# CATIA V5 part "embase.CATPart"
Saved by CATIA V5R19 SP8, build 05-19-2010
Part number: embase avant
Bounding box of the stored display mesh (mm): x 0 to 230, y -25 to 25, z 0 to 44
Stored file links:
  G:\EU_thinkMotion\CFAO_2010\MMS_groupe2\MMS_groupe2\A reprendre\rbouchet\rbouchet_Catia\embase.CATPart
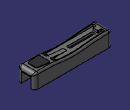
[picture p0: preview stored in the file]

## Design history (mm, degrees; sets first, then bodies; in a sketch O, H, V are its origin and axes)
Set1
  Plane1: type Offset, RefPlane xy-plane, Offset 40
Body1 (main body)
  Sketch1 on yz-plane, origin (0, 0, 0), H (0, 1, 0), V (0, 0, 1)
    line L1 (-25, 0) -> (-25, 45)
    point P1 (-25, 0)
    line L2 (-25, 45) -> (25, 45)
    line L3 (25, 45) -> (25, 0)
    point P4 (25, 0)
    line L4 (25, 0) -> (15, 0)
    line L5 (15, 0) -> (15, 30)
    line L6 (15, 30) -> (-15, 30)
    line L7 (-15, 30) -> (-15, 0)
    line L8 (-15, 0) -> (-25, 0)
    point P9 (-25, 0)
    length L6 = 30
    length L8 = 10
    length L4 = 10
    length L1 = 45
    length L3 = 45
    length L7 = 30
    length L5 = 30
    distance V L5 = 15
    coincidence: P1 H, P4 H, P1 P9
    horizontal: L2 H, L4 H, L6 H, L8 H
    vertical: L3 V, L5 V
  Pad1: profile Sketch1, direction (1, 0, 0), length 230
  Sketch2 on face of Pad1 from Sketch1.L3, origin (0, 25, 0), H (-1, 0, 0), V (0, 0, 1)
    spline S1 through (-230, 43) (-219.336, 42.8754) (-173.9652, 41.983) (-134.5252, 37.5213) (-64.8381, 40.4958) (-28.6601, 42.922) (0, 43)
    reference projected line E1 (-230, 0) -> (-230, 45) from edge [face of Pad1 from Sketch1.L3 | end face of Pad1]
    reference projected line E2 (0, 45) -> (-230, 45) from edge [face of Pad1 from Sketch1.L2 | face of Pad1 from Sketch1.L3]
    reference projected line E3 (0, 45) -> (-230, 45) from edge [face of Pad1 from Sketch1.L2 | face of Pad1 from Sketch1.L3]
    reference projected line E4 (0, 0) -> (0, 45) from edge [start face of Pad1 | face of Pad1 from Sketch1.L3]
    point P1 (0, 43)
    point P2 (-230, 43)
    distance P2 E2 = 2
    distance P1 E3 = 2
    coincidence: P1 V, E1 P2, P1 E4
  Pocket1: profile Sketch2, direction (0, -1, 0), length 230
  Fillet1: radius 5, on edge [face of Pad1 from Sketch1.L3 | face of Pocket1 from Sketch2.S1]; edge [face of Pad1 from Sketch1.L1 | face of Pocket1 from Sketch2.S1]
  Fillet2: radius 10, on edge [start face of Pad1 | face of Pocket1 from Sketch2.S1]; edge [face of Pocket1 from Sketch2.S1 | end face of Pad1]; edge [face of Pad1 from Sketch1.L1 | end face of Pad1]; edge [face of Pad1 from Sketch1.L3 | end face of Pad1]
  Sketch3 on face of Pad1 from Sketch1.L2, origin (0, 0, 45), H (1, 0, 0), V (0, 1, 0)
    line L1 (15, 17.5) -> (15, 7.5)
    line L2 (15, 17.5) -> (165, 17.5)
    line L3 (165, 17.5) -> (165, 6)
    line L4 (165, 6) -> (115, 6)
    line L5 (115, 6) -> (115, -6)
    line L6 (115, -6) -> (165, -6)
    point P7 (165, -6)
    line L7 (165, -6) -> (165, -17.5)
    line L8 (165, -17.5) -> (15, -17.5)
    point P9 (15, -17.5)
    line L9 (15, -17.5) -> (15, -7.5)
    line L10 (15, -7.5) -> (25, -7.5)
    line L11 (25, -7.5) -> (25, 7.5)
    line L12 (25, 7.5) -> (15, 7.5)
    reference projected line E1 (0, 25) -> (230, 25) from edge [face of Pad1 from Sketch1.L2 | face of Pad1 from Sketch1.L3]
    reference projected line E2 (0, 25) -> (0, -25) from edge [start face of Pad1 | face of Pad1 from Sketch1.L2]
    length L2 = 150
    distance L11 L5 = 90
    length L1 = 10
    length L11 = 15
    length L9 = 10
    distance L2 E1 = 7.5
    length L12 = 10
    distance L1 E2 = 15
    distance L4 L6 = 12
    length L3 = 11.5
    vertical: L1 V, L3 V, L5 V, L7 V, L9 V, L11 V
    horizontal: L2 H, L4 H, L6 H, L8 H, L10 H, L12 H
    coincidence: P7 L3, P9 L1
  Pocket2: profile Sketch3, direction (0, 0, -1), length 10
  Fillet3: radius 1, on edge [face of Pocket2 from Sketch3.L1 | face of Pocket2 from Sketch3.L2]; edge [face of Pocket2 from Sketch3.L12 | face of Pocket2 from Sketch3.L1]; edge [face of Pocket2 from Sketch3.L11 | face of Pocket2 from Sketch3.L12]; edge [face of Pocket2 from Sketch3.L10 | face of Pocket2 from Sketch3.L11]; edge [face of Pocket2 from Sketch3.L8 | face of Pocket2 from Sketch3.L9]; edge [face of Pocket2 from Sketch3.L9 | face of Pocket2 from Sketch3.L10]; edge [face of Pocket2 from Sketch3.L2 | face of Pocket2 from Sketch3.L3]; edge [face of Pocket2 from Sketch3.L4 | face of Pocket2 from Sketch3.L5]; edge [face of Pocket2 from Sketch3.L5 | face of Pocket2 from Sketch3.L6]; edge [face of Pocket2 from Sketch3.L6 | face of Pocket2 from Sketch3.L7]; edge [face of Pocket2 from Sketch3.L7 | face of Pocket2 from Sketch3.L8]; edge [face of Pocket2 from Sketch3.L3 | face of Pocket2 from Sketch3.L4]
  Sketch4 on Plane1, origin (0, 0, 40), H (1, 0, 0), V (0, 1, 0)
    line L1 (175, 12.5) -> (175, -12.5)
    point P1 (175, 12.5)
    point P3 (181.043, -13.904)
    point P4 (206.043, -13.904)
    line L2 (212, -8.5) -> (212, 8.5)
    point P5 (212, -8.5)
    point P6 (212, 8.5)
    point P7 (181.1672, 13.2821)
    reference projected line E1 through (220, 0) direction (0, 1) from axis of face of Fillet2
    line L3 (182.4779, 17.5) -> (207.0981, 13.1588)
    point P9 (182.4779, 17.5)
    connectcurve C1
    line L4 (180.9327, -17.5) -> (205.8376, -15.3211)
    point P10 (180.9327, -17.5)
    connectcurve C2
    connectcurve C3
    connectcurve C4
    reference projected line E2 (165, 17.5) -> (165, 6) from edge [face of Pocket2 from Sketch3.L3 | face of Pocket1 from Sketch2.S1]
    reference projected line E3 (15, 17.5) -> (165, 17.5) from edge [face of Pocket2 from Sketch3.L2 | face of Pocket1 from Sketch2.S1]
    reference projected line E4 (15, 17.5) -> (165, 17.5) from edge [face of Pocket2 from Sketch3.L2 | face of Pocket1 from Sketch2.S1]
    reference projected line E5 (165, -17.5) -> (15, -17.5) from edge [face of Pocket2 from Sketch3.L8 | face of Pocket1 from Sketch2.S1]
    reference projected line E6 (165, -17.5) -> (15, -17.5) from edge [face of Pocket2 from Sketch3.L8 | face of Pocket1 from Sketch2.S1]
    reference projected line E7 (15, 17.5) -> (165, 17.5) from edge [face of Pocket2 from Sketch3.L2 | face of Pocket1 from Sketch2.S1]
    length L1 = 25
    distance L2 E1 = 8
    angle L1 L3 = 80
    angle L1 L4 = 85
    distance L1 E2 = 10
    distance E3 P1 = 5
    length L3 = 25
    length L4 = 25
    distance P9 E4 = 0
    distance P10 E5 = 0
    distance P5 E6 = 9
    distance P6 E7 = 9
    vertical: L1 V, L2 V
  Pad2: profile Sketch4, direction (0, 0, 1), length 4
  Fillet4: radius 0.2, on edge [face of Pocket1 from Sketch2.S1 | face of Pad2 from Sketch4.L1]; edge [face of Pocket1 from Sketch2.S1 | face of Pad2 from Sketch4.C4]; edge [face of Pocket1 from Sketch2.S1 | face of Pad2 from Sketch4.L4]; edge [face of Pad2 from Sketch4.C2 | face of Pocket1 from Sketch2.S1]; edge [face of Pad2 from Sketch4.C3 | face of Pocket1 from Sketch2.S1]; edge [face of Pad2 from Sketch4.L3 | face of Pocket1 from Sketch2.S1]; edge [face of Pocket1 from Sketch2.S1 | face of Pad2 from Sketch4.C1]; face of Pocket1 from Sketch2.S1; end face of Pad2
  Sketch5 on face of Pocket2 from Sketch3.L8, origin (0, -17.5, 0), H (-1, 0, 0), V (0, 0, 1)
    circle A1 centre (-160.9607, 38.808) radius 1.5
    point P1 (-160.9607, 38.808)
    reference projected line E1 (-165, 35) -> (-15, 35) from edge [face of Pocket2 from Sketch3.L8 | end face of Pocket2]
    radius A1 = 1.5
    distance P1 E1 = 3.808
  Pocket3: profile Sketch5, direction (0, -1, 0), length 3
  RectPattern1: of Pocket3, direction 1 instances 2, spacing 14.5, along edge [face of Pocket2 from Sketch3.L7 | face of Fillet4] reversed
  RectPattern2: of Pocket3, direction 1 instances 2, spacing 23.5, along edge [face of Pocket2 from Sketch3.L7 | face of Fillet4] reversed
  RectPattern3: of Pocket3, direction 1 instances 2, spacing 38, along edge [face of Pocket2 from Sketch3.L7 | face of Fillet4] reversed
  Sketch6 on end face of Pocket2, origin (0, 0, 35), H (1, 0, 0), V (0, 1, 0)
    line L1 (15, 17.5) -> (155.1781, 17.5)
    line L2 (155.1781, 17.5) -> (155.1781, 6)
    line L3 (155.1781, 6) -> (115, 6)
    line L4 (115, 6) -> (115, -6)
    line L5 (115, -6) -> (155.1781, -6)
    point P6 (155.1781, -6)
    line L6 (155.1781, -6) -> (155.1781, -17.5)
    line L7 (155.1781, -17.5) -> (15, -17.5)
    line L8 (15, -17.5) -> (15, -7.5)
    line L9 (15, -7.5) -> (25, -7.5)
    line L10 (25, -7.5) -> (25, 7.5)
    line L11 (25, 7.5) -> (15, 7.5)
    line L12 (15, 7.5) -> (15, 17.5)
    reference projected line E1 (165.1781, 16.5) -> (165.1781, 7) from edge [face of Fillet4 | face of Pocket1 from Sketch2.S1]
    reference projected line E2 (15, 17.5) -> (165, 17.5) from edge [face of Pocket2 from Sketch3.L2 | end face of Pocket2]
    reference projected line E3 (165, -17.5) -> (15, -17.5) from edge [face of Pocket2 from Sketch3.L8 | end face of Pocket2]
    reference projected line E4 (165, 6) -> (115, 6) from edge [face of Pocket2 from Sketch3.L4 | end face of Pocket2]
    reference projected line E5 (115, 6) -> (115, -6) from edge [face of Pocket2 from Sketch3.L5 | end face of Pocket2]
    reference projected line E6 (115, -6) -> (165, -6) from edge [face of Pocket2 from Sketch3.L6 | end face of Pocket2]
    reference projected line E7 (15, -17.5) -> (15, -7.5) from edge [face of Pocket2 from Sketch3.L9 | end face of Pocket2]
    reference projected line E8 (15, -7.5) -> (25, -7.5) from edge [face of Pocket2 from Sketch3.L10 | end face of Pocket2]
    reference projected line E9 (25, -7.5) -> (25, 7.5) from edge [face of Pocket2 from Sketch3.L11 | end face of Pocket2]
    reference projected line E10 (25, 7.5) -> (15, 7.5) from edge [face of Pocket2 from Sketch3.L12 | end face of Pocket2]
    reference projected line E11 (15, 7.5) -> (15, 17.5) from edge [face of Pocket2 from Sketch3.L1 | end face of Pocket2]
    distance L2 E1 = 10
    distance L1 E2 = 0
    distance L7 E3 = 0
    distance L3 E4 = 0
    distance L4 E5 = 0
    distance L5 E6 = 0
    distance E7 L8 = 0
    distance E8 L9 = 0
    distance L10 E9 = 0
    distance L11 E10 = 0
    distance L12 E11 = 0
    horizontal: L1 H, L3 H, L5 H, L7 H, L9 H, L11 H
    vertical: L2 V, L4 V, L6 V, L8 V, L10 V, L12 V
    coincidence: P6 L2
  Pad3: profile Sketch6, direction (0, 0, 1), length 1.64
  Sketch7 on end face of Pad3, origin (0, 0, 36.64), H (1, 0, 0), V (0, 1, 0)
    line L1 (30, 5) -> (105, 5)
    line L2 (105, 5) -> (105, -5)
    line L3 (105, -5) -> (30, -5)
    line L4 (30, -5) -> (30, 5)
    reference intersected line E1 (15, 17.5) -> (165, 17.5) from face of Pocket2 from Sketch3.L2
    reference projected line E2 (25, 6.5) -> (25, -6.5) from edge [face of Pocket2 from Sketch3.L11 | end face of Pad3]
    length L1 = 75
    length L4 = 10
    distance L1 E1 = 12.5
    distance E2 L4 = 5
    horizontal: L1 H, L3 H
    vertical: L2 V, L4 V
  Pocket4: profile Sketch7, direction (0, 0, -1), through (limit type 6)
